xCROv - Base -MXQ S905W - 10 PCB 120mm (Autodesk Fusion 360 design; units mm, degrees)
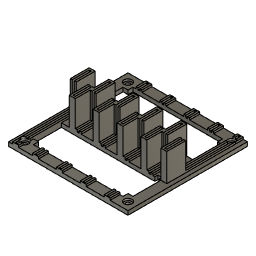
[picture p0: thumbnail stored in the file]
sketch "Shelf" plane through (0, 0, 0) normal (0, 0, 1) x axis (1, 0, 0)
  line L1 (-6, 0) -> (0, 0)
  line L2 (-6, 75) -> (-6, 0)
  line L3 (0, 75) -> (-6, 75)
  line L4 (0, 0) -> (0, 75)
  line L5 (-4, 1) -> (-2, 1)
  line L6 (-4, 73) -> (-4, 1)
  line L7 (-2, 73) -> (-4, 73)
  line L8 (-2, 1) -> (-2, 73)
  line L9 (-4, 58) -> (-6, 58)
  line L10 (0, 58) -> (-2, 58)
  point P1 (0, 0)
  point P2 (0, 0)
  point P10 (-6, 58)
  point P11 (-4, 58)
  point P12 (-2, 58)
  point P13 (0, 58)
  point P3 (-6, 0)
  point P5 (0, 75)
  horizontal L1
  vertical L2
  horizontal L3
  vertical L4
  coincident P1 P2
  horizontal L5
  vertical L6
  horizontal L7
  vertical L8
  coincident L2 P10
  coincident L6 P11
  perpendicular L6 L9
  coincident L8 P12
  coincident L4 P13
  perpendicular L4 L10
  dimension "d9" distance P2 P3 = 6
  dimension "d10" distance P2 P5 = 75
  dimension "d11" distance L7 L9 = 15
  dimension "d12" distance L7 L10 = 15
extrude "Extrude1" new body sketch "Shelf" along normal blind 4 bodies "ATV1"
extrude "Extrude2" add sketch "Shelf" profile of L2 L3 L4 L6 L7 L8 L9 L10 along normal blind 15
box_primitive "BoxPrimitive1" DistanceX 75 DistanceY 6 DistanceZ 2 OffsetDistanceX 0 OffsetDistanceY 0
extrude "Extrude3" add of existing geometry blind 2
offset_faces "OffsetFaces1" distance -2
offset_faces "OffsetFaces2" distance 15
sketch "Base" plane through (0, 0, 0) normal (0, 0, 1) x axis (1, 0, 0)
  line L1 (-98, 0) -> (0, 0)
  line L2 (-98, 77.0062) -> (-98, 0)
  line L3 (0, 77.0062) -> (-98, 77.0062)
  line L4 (0, 0) -> (0, 77.0062)
  point P1 (0, 0)
  point P2 (0, 0)
  point P3 (-98, 0)
  horizontal L1
  vertical L2
  horizontal L3
  vertical L4
  coincident P1 P2
  dimension "d26" distance P2 P3 = 98
extrude "Extrude4" new body sketch "Base" along normal blind 2 bodies "base"
copy_paste_bodies "CopyPasteBodies1"
move "Move1"
copy_paste_bodies "CopyPasteBodies2"
move "Move2"
copy_paste_bodies "CopyPasteBodies3"
move "Move3"
move "Move4"
move "Move5"
copy_paste_bodies "CopyPasteBodies4"
move "Move6"
move "Move7"
move "Move9"
move "Move10"
move "Move11"
offset_faces "OffsetFaces3" distance 22
move "Move12"
move "Move13"
move "Move14"
move "Move15"
move "Move16"
move "Move17"
move "Move18"
move "Move19"
move "Move20"
move "Move21"
move "Move22"
move "Move23"
move "Move24"
remove_body "RemoveBody1"
remove_body "RemoveBody2"
remove_body "RemoveBody3"
remove_body "RemoveBody4"
remove_body "RemoveBody5"
remove_body "RemoveBody6"
copy_paste_bodies "CopyPasteBodies5"
move "Move25"
move "Move26"
move "Move27"
move "Move28"
sketch "Fan Base" plane through (0, 0, 0) normal (0, 0, 1) x axis (1, 0, 0)
  line L1 (0, 75) -> (-120, 75)
  line L2 (0, 55) -> (0, 75)
  line L3 (-120, 55) -> (0, 55)
  line L4 (-120, 75) -> (-120, 55)
  line L5 (-110, 5) -> (0, 5)
  line L6 (-110, 15) -> (-110, 5)
  line L7 (0, 15) -> (-110, 15)
  line L8 (0, 5) -> (0, 15)
  line L9 (-110, 5) -> (-120, 5)
  line L10 (-110, 115) -> (-110, 5)
  line L11 (-120, 115) -> (-110, 115)
  line L12 (-120, 5) -> (-120, 115)
  line L13 (-10, 115) -> (-120, 115)
  line L14 (-10, 125) -> (-10, 115)
  line L15 (-120, 125) -> (-10, 125)
  line L16 (-120, 115) -> (-120, 125)
  line L17 (-10, 125) -> (0, 125)
  line L18 (-10, 15) -> (-10, 125)
  line L19 (0, 15) -> (-10, 15)
  line L20 (0, 125) -> (0, 15)
  line L21 (-105, 15) -> (-110, 15)
  line L22 (-105, 20) -> (-105, 15)
  line L23 (-110, 20) -> (-105, 20)
  line L24 (-110, 15) -> (-110, 20)
  line L25 (-15, 15) -> (-10, 15)
  line L26 (-15, 20) -> (-15, 15)
  line L27 (-10, 20) -> (-15, 20)
  line L28 (-10, 15) -> (-10, 20)
  line L29 (-15, 115) -> (-10, 115)
  line L30 (-15, 110) -> (-15, 115)
  line L31 (-10, 110) -> (-15, 110)
  line L32 (-10, 115) -> (-10, 110)
  line L33 (-105, 115) -> (-110, 115)
  line L34 (-105, 110) -> (-105, 115)
  line L35 (-110, 110) -> (-105, 110)
  line L36 (-110, 115) -> (-110, 110)
  circle C1 centre (-112, 117) radius 2
  circle C2 centre (-8, 13) radius 2
  circle C3 centre (-112, 13) radius 2
  circle C4 centre (-8, 117) radius 2
  point P19 (-10, 15)
  point P21 (-112, 117)
  point P23 (-112, 13)
  point P22 (-8, 13)
  point P24 (-8, 117)
  horizontal L1
  vertical L2
  horizontal L3
  vertical L4
  horizontal L5
  vertical L6
  horizontal L7
  vertical L8
  horizontal L9
  vertical L10
  horizontal L11
  vertical L12
  horizontal L13
  vertical L14
  horizontal L15
  vertical L16
  horizontal L17
  vertical L18
  horizontal L19
  vertical L20
  coincident L7 P19
  horizontal L21
  vertical L22
  horizontal L23
  vertical L24
  horizontal L25
  vertical L26
  horizontal L27
  vertical L28
  horizontal L29
  vertical L30
  horizontal L31
  vertical L32
  horizontal L33
  vertical L34
  horizontal L35
  vertical L36
  dimension "d49" distance L15 P21 = 8
  dimension "d50" distance L16 P21 = 8
  dimension "d51" distance L12 P23 = 8
  dimension "d52" distance L9 P23 = 8
  dimension "d53" distance L8 P22 = 8
  dimension "d54" distance L5 P22 = 8
  dimension "d56" distance L20 P24 = 8
  dimension "d57" distance L17 P24 = 8
delete_face "DeleteFace1"
box_primitive "BoxPrimitive2" DistanceX 2 DistanceY 34 DistanceZ 1 OffsetDistanceX 0 OffsetDistanceY 0
move "Move29"
extrude "Extrude8" add of existing geometry blind 105 bodies "ATV1.1", "ATV2.1", "ATV3.1", "ATV4.1", "ATV1.2", "ATV2.2", "ATV3.2", "ATV4.2"
combine "Combine3"
sketch "Notch" plane through (0, 0, 0) normal (0, 0, 1) x axis (1, 0, 0)
  line L1 (-16, 48) -> (-12, 48)
  line L2 (-16, 51) -> (-16, 48)
  line L3 (-12, 51) -> (-16, 51)
  line L4 (-12, 48) -> (-12, 51)
  line L5 (-104, 82) -> (-108, 82)
  line L6 (-104, 79) -> (-104, 82)
  line L7 (-108, 79) -> (-104, 79)
  line L8 (-108, 82) -> (-108, 79)
  point P2 (-12, 48)
  point P3 (-16, 48)
  horizontal L1
  vertical L2
  horizontal L3
  vertical L4
  horizontal L5
  vertical L6
  horizontal L7
  vertical L8
  dimension "d65" distance P2 P3 = 4
extrude "Extrude9" cut sketch "Notch" profile of L5 L6 L7 L8 along normal blind 2
extrude "Extrude10" cut sketch "Notch" profile of L1 L2 L3 L4 along normal blind 2
extrude "Extrude11" add sketch "Fan Base" profile of L1 L2 L3 L4 L5 L6 L7 L8 L9 L10 L11 L12 L13 L14 L15 L16 L17 L18 L19 L20 C1 C2 C3 C4 along normal blind 2
sketch "PCB Rail Void" plane through (0, 0, 0) normal (0, 0, 1) x axis (1, 0, 0)
  line L1 (-10, 15) -> (-110, 15)
  line L2 (-10, 48) -> (-10, 15)
  line L3 (-110, 48) -> (-10, 48)
  line L4 (-110, 15) -> (-110, 48)
  line L5 (-10, 115) -> (-110, 115)
  line L6 (-10, 82) -> (-10, 115)
  line L7 (-110, 82) -> (-10, 82)
  line L8 (-110, 115) -> (-110, 82)
  horizontal L1
  vertical L2
  horizontal L3
  vertical L4
  horizontal L5
  vertical L6
  horizontal L7
  vertical L8
extrude "Extrude12" cut sketch "PCB Rail Void" along normal blind 20
extrude "Extrude13" cut sketch "Fan Base" profile of C1 C2 C3 C4 along normal blind 19
extrude "Extrude14" new body sketch "Fan Base" profile of L7 L10 L13 L18 L21 L22 L23 L24 L25 L26 L27 L28 L29 L30 L31 L32 L33 L34 L35 L36 along normal blind 2
combine "Combine4" bodies "ATV5.1"
hole "Hole1" HoleDepth 1 HoleDiameter 4 TipAngle 180 CBDepth 1 CBDiameter 8
extrude "Extrude15" cut of existing geometry blind 9
hole "Hole2" HoleDepth 1 HoleDiameter 4 TipAngle 180 CBDepth 1 CBDiameter 8
hole "Hole3" HoleDepth 1 HoleDiameter 4 TipAngle 180 CBDepth 1 CBDiameter 8
extrude "Extrude16" cut of existing geometry blind 30
hole "Hole4" HoleDepth 1 HoleDiameter 4 TipAngle 180 CBDepth 1 CBDiameter 8
extrude "Extrude17" add of existing geometry blind 2
offset_faces "OffsetFaces4" distance -1
extrude "Extrude18" cut of existing geometry blind -1
extrude "Extrude19" cut of existing geometry blind -1
extrude "Extrude20" cut of existing geometry blind -1
extrude "Extrude5" add sketch "Fan Base" profile of L1 L2 L3 L4 against normal blind 4 bodies "ATV2.1", "ATV3.1", "ATV4.1", "ATV5.1", "base (1)", "ATV1.2", "ATV2.2", "ATV3.2"
extrude "Extrude6" add sketch "Fan Base" profile of L1 L3 against normal blind 4
extrude "Extrude7" cut of existing geometry blind -2
combine "Combine1" bodies "ATV4", "ATV2", "ATV3", "base", "ATV5"
combine "Combine2" bodies "ATV2.1", "ATV3.1", "ATV4.1", "ATV5.1", "base (1)"
sketch "Sketch14" plane through (0, 0, 0) normal (0, 0, 1) x axis (1, 0, 0)
move "Move8" TranslateX 0 TranslateY 10 TranslateZ 0
sketch "Sketch11" plane through (-12.9211, -23.0211, 17.5) normal (0, 0, 1) x axis (-1, 0, 0)
sketch "Sketch12" plane through (74.0417, 0, 0) normal (1, 0, 0) x axis (0, 1, 0)
  line L1 (20.4803, 0.9092) -> (19.75, 0)
  line L2 (21.2453, 1.7893) -> (20.4803, 0.9092)
  line L3 (22.044, 2.639) -> (21.2453, 1.7893)
  line L4 (22.8751, 3.457) -> (22.044, 2.639)
  line L5 (23.7373, 4.2421) -> (22.8751, 3.457)
  line L6 (24.6294, 4.9931) -> (23.7373, 4.2421)
  line L7 (25.5501, 5.7089) -> (24.6294, 4.9931)
  line L8 (26.4978, 6.3883) -> (25.5501, 5.7089)
  line L9 (27.4713, 7.0304) -> (26.4978, 6.3883)
  line L10 (28.4689, 7.6342) -> (27.4713, 7.0304)
  line L11 (29.4893, 8.1988) -> (28.4689, 7.6342)
  line L12 (30.5308, 8.7232) -> (29.4893, 8.1988)
  line L13 (31.592, 9.2068) -> (30.5308, 8.7232)
  line L14 (32.6711, 9.6488) -> (31.592, 9.2068)
  line L15 (33.7666, 10.0485) -> (32.6711, 9.6488)
  line L16 (34.8768, 10.4054) -> (33.7666, 10.0485)
  line L17 (36, 10.7188) -> (34.8768, 10.4054)
  line L18 (37.1346, 10.9883) -> (36, 10.7188)
  line L19 (38.2788, 11.2136) -> (37.1346, 10.9883)
  line L20 (39.4308, 11.3942) -> (38.2788, 11.2136)
  line L21 (40.5891, 11.5298) -> (39.4308, 11.3942)
  line L22 (41.7517, 11.6204) -> (40.5891, 11.5298)
  line L23 (42.9169, 11.6657) -> (41.7517, 11.6204)
  line L24 (44.0831, 11.6657) -> (42.9169, 11.6657)
  line L25 (45.2483, 11.6204) -> (44.0831, 11.6657)
  line L26 (46.4109, 11.5298) -> (45.2483, 11.6204)
  line L27 (47.5692, 11.3942) -> (46.4109, 11.5298)
  line L28 (48.7212, 11.2136) -> (47.5692, 11.3942)
  line L29 (49.8654, 10.9883) -> (48.7212, 11.2136)
  line L30 (51, 10.7188) -> (49.8654, 10.9883)
  line L31 (52.1232, 10.4054) -> (51, 10.7188)
  line L32 (53.2334, 10.0485) -> (52.1232, 10.4054)
  line L33 (54.3289, 9.6488) -> (53.2334, 10.0485)
  line L34 (55.408, 9.2068) -> (54.3289, 9.6488)
  line L35 (56.4692, 8.7232) -> (55.408, 9.2068)
  line L36 (57.5107, 8.1988) -> (56.4692, 8.7232)
  line L37 (58.5311, 7.6342) -> (57.5107, 8.1988)
  line L38 (59.5287, 7.0304) -> (58.5311, 7.6342)
  line L39 (60.5022, 6.3883) -> (59.5287, 7.0304)
  line L40 (61.4499, 5.7089) -> (60.5022, 6.3883)
  line L41 (62.3706, 4.9931) -> (61.4499, 5.7089)
  line L42 (63.2627, 4.2421) -> (62.3706, 4.9931)
  line L43 (64.1249, 3.457) -> (63.2627, 4.2421)
  line L44 (64.956, 2.639) -> (64.1249, 3.457)
  line L45 (65.7547, 1.7893) -> (64.956, 2.639)
  line L46 (66.5197, 0.9092) -> (65.7547, 1.7893)
  line L47 (67.25, 0) -> (66.5197, 0.9092)
  line L48 (87, 0) -> (67.25, 0)
  line L49 (87, 17.5) -> (87, 0)
  line L50 (0, 17.5) -> (87, 17.5)
  line L51 (0, 0) -> (0, 17.5)
  line L52 (19.75, 0) -> (0, 0)
  line L53 (87, 17.5) -> (0, 17.5)
  line L54 (87, 0) -> (87, 17.5)
  line L55 (0, 0) -> (87, 0)
  line L56 (0, 17.5) -> (0, 0)
  point P50 (87, 0)
  point P56 (87, 0)
  point P52 (0, 17.5)
  point P54 (0, 17.5)
  horizontal L53
  vertical L54
  horizontal L55
  vertical L56
  coincident P50 P56
  coincident P52 P54
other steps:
base_feature "Base Feature1" bodies "ATV2"
base_feature "Base Feature2" bodies "ATV1", "ATV2", "ATV3", "ATV4"
base_feature "Base Feature3" bodies "ATV4", "ATV5"
base_feature "Base Feature4" bodies "ATV1 (1)", "ATV2 (1)", "ATV3", "ATV4 (1)", "ATV5", "base", "ATV1.1", "ATV2.1"
base_feature "Base Feature5" bodies "ATV1.1", "ATV2.1", "ATV3.1", "base (1)", "ATV4.1", "ATV5.1", "ATV1.2", "ATV2.2"
named bodies: "ATV1", "base", "ATV2", "ATV3", "ATV4", "ATV5", "ATV1 (1)", "ATV2 (1)", "ATV4 (1)", "ATV1.1", "ATV2.1", "ATV3.1", "ATV4.1", "ATV5.1", "base (1)", "ATV1.2", "ATV2.2", "ATV3.2", "base.2", "ATV4.2", "ATV5.2"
